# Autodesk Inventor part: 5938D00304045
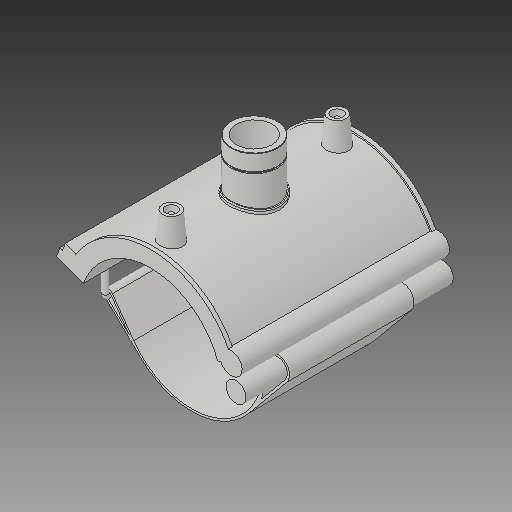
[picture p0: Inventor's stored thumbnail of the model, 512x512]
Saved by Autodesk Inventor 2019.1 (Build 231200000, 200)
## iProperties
Created: 2017-07
Part Number: 5938D00304045
Material: Generic
Description: PLASSON TRANSITION SADDLE 4''DIPS x 1"NPT
Document SubType Name: Modeling
Designer: KIM
Density: 1 g/cm^3
Appearance: Default
Author: KIM
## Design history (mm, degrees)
derived "5938D.ipt"
feature "Solid1::5938D.ipt"
tag "TaggingFeature1"
body "Solid1"
other parameters: "d_" = 121.3, "B_" = 165.1, "H_" = 41.91, "L_" = 176.022, "d_t" = 6, "G_" = 30.291, "d148" = 1.8195, "d160" = 1.8195, "d169" = 1.8195, "d192" = 4.852, "d0" = 121.3, "d1" = 145.56, "d2" = 412.75, "d3" = 30.325, "d4" = 176.022, "d5" = 0, "d40" = 75.6912, "d41" = 42.4074, "d43" = 0, "d45" = 0, "d47" = 114.69, "d48" = 39.3783, "d50" = 0, "d78" = 94.78, "d79" = 15, "d80" = 70.4088, "d82" = 5 deg, "d84" = 4, "d85" = 14, "d86" = 0, "d87" = 3, "d88" = 0, "d96" = 148.4712, "d97" = 3.52044, "d98" = 0, "d102" = 0.90873, "d103" = 30.291, "d104" = 25.146, "d105" = 0, "d106" = 24.2328, "d108" = 0, "d109" = -13.97, "d111" = 0.5, "d112" = 0.5, "d113" = 0, "d114" = 0.5, "d117" = 0.30291, "d120" = 140 deg, "d121" = 24.228, "d122" = 20 deg, "d123" = 582.24, "d124" = 87.336, "d126" = 0, "d143" = 124.939, "d145" = 18.66154, "d149" = 1.8195, "d150" = 20.52769, "d153" = 176.022, "d154" = 0, "d156" = 72.78, "d157" = 160 deg, "d159" = 4.852, "d161" = 1.8195, "d162" = 105.6132, "d163" = 0, "d164" = 60.65, "d167" = 12.13, "d168" = 71.00488, "d170" = 1.8195, "d172" = 0, "d173" = 1, "d175" = 60.65, "d176" = 20 deg, "d177" = 8.491, "d178" = 24.26, "d180" = 0, "d183" = 9.704, "d184" = 6.7928, "d185" = 57.20715, "d186" = 57.20715, "d187" = 72.78, "d188" = 7.278, "d189" = 8.491, "d190" = 0, "d191" = 87.336, "d193" = 4.852, "d194" = 2.48665, "d195" = 90 deg, "d197" = 0, "d199" = 0
